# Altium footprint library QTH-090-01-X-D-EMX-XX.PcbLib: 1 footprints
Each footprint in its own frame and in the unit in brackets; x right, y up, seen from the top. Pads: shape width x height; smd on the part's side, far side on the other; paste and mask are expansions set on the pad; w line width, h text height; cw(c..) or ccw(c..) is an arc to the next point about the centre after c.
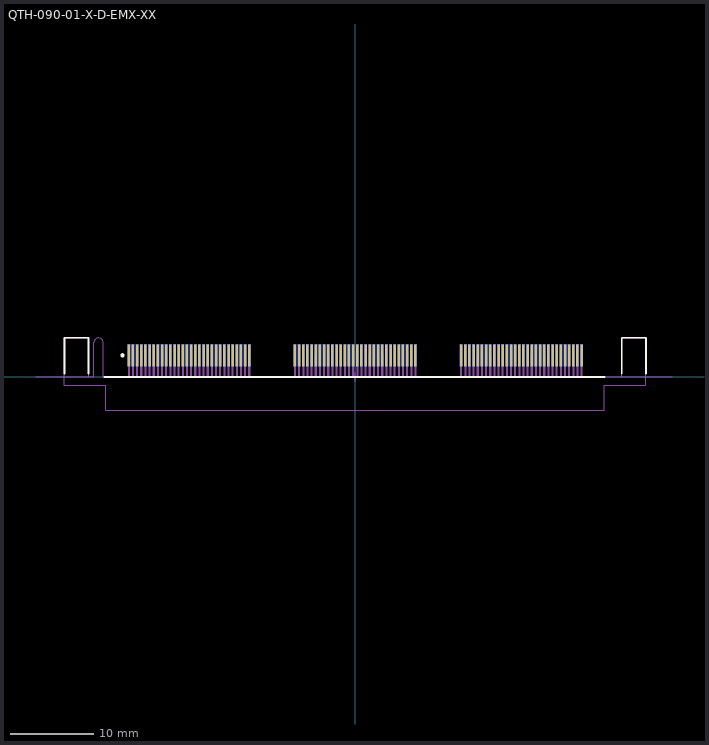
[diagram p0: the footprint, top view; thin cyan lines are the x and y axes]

## QTH-090-01-X-D-EMX-XX [mm] "0.50mm pitch, 180 pin, high speed terminal; w/edge mounts"
height 3.62
pads (180):
  rect 0.3x2.65 smd mask+0: 1(-27.253,2.6) 3(-26.753,2.6) 5(-26.253,2.6) 7(-25.753,2.6) 9(-25.253,2.6) 11(-24.753,2.6) 13(-24.253,2.6) 15(-23.753,2.6) 17(-23.253,2.6) 19(-22.753,2.6) 21(-22.253,2.6) 23(-21.753,2.6) 25(-21.253,2.6) 27(-20.753,2.6) 29(-20.253,2.6) 31(-19.753,2.6) 33(-19.253,2.6) 35(-18.753,2.6) 37(-18.253,2.6) 39(-17.753,2.6) 41(-17.253,2.6) 43(-16.753,2.6) 45(-16.253,2.6) 47(-15.753,2.6) 49(-15.253,2.6) 51(-14.753,2.6) 53(-14.253,2.6) 55(-13.753,2.6) 57(-13.253,2.6) 59(-12.753,2.6) 61(-7.25,2.6) 63(-6.75,2.6) 65(-6.25,2.6) 67(-5.75,2.6) 69(-5.25,2.6) 71(-4.75,2.6) 73(-4.25,2.6) 75(-3.75,2.6) 77(-3.25,2.6) 79(-2.75,2.6) 81(-2.25,2.6) 83(-1.75,2.6) 85(-1.25,2.6) 87(-0.75,2.6) 89(-0.25,2.6) 91(0.25,2.6) 93(0.75,2.6) 95(1.25,2.6) 97(1.75,2.6) 99(2.25,2.6) 101(2.75,2.6) 103(3.25,2.6) 105(3.75,2.6) 107(4.25,2.6) 109(4.75,2.6) 111(5.25,2.6) 113(5.75,2.6) 115(6.25,2.6) 117(6.75,2.6) 119(7.25,2.6) 121(12.753,2.6) 123(13.253,2.6) 125(13.753,2.6) 127(14.253,2.6) 129(14.753,2.6) 131(15.253,2.6) 133(15.753,2.6) 135(16.253,2.6) 137(16.753,2.6) 139(17.253,2.6) 141(17.753,2.6) 143(18.253,2.6) 145(18.753,2.6) 147(19.253,2.6) 149(19.753,2.6) 151(20.253,2.6) 153(20.753,2.6) 155(21.253,2.6) 157(21.753,2.6) 159(22.253,2.6) 161(22.753,2.6) 163(23.253,2.6) 165(23.753,2.6) 167(24.253,2.6) 169(24.753,2.6) 171(25.253,2.6) 173(25.753,2.6) 175(26.253,2.6) 177(26.753,2.6) 179(27.253,2.6)
  rect 0.3x2.65 smd far side mask+0: 2(-27.253,2.6) 4(-26.753,2.6) 6(-26.253,2.6) 8(-25.753,2.6) 10(-25.253,2.6) 12(-24.753,2.6) 14(-24.253,2.6) 16(-23.753,2.6) 18(-23.253,2.6) 20(-22.753,2.6) 22(-22.253,2.6) 24(-21.753,2.6) 26(-21.253,2.6) 28(-20.753,2.6) 30(-20.253,2.6) 32(-19.753,2.6) 34(-19.253,2.6) 36(-18.753,2.6) 38(-18.253,2.6) 40(-17.753,2.6) 42(-17.253,2.6) 44(-16.753,2.6) 46(-16.253,2.6) 48(-15.753,2.6) 50(-15.253,2.6) 52(-14.753,2.6) 54(-14.253,2.6) 56(-13.753,2.6) 58(-13.253,2.6) 60(-12.753,2.6) 62(-7.25,2.6) 64(-6.75,2.6) 66(-6.25,2.6) 68(-5.75,2.6) 70(-5.25,2.6) 72(-4.75,2.6) 74(-4.25,2.6) 76(-3.75,2.6) 78(-3.25,2.6) 80(-2.75,2.6) 82(-2.25,2.6) 84(-1.75,2.6) 86(-1.25,2.6) 88(-0.75,2.6) 90(-0.25,2.6) 92(0.25,2.6) 94(0.75,2.6) 96(1.25,2.6) 98(1.75,2.6) 100(2.25,2.6) 102(2.75,2.6) 104(3.25,2.6) 106(3.75,2.6) 108(4.25,2.6) 110(4.75,2.6) 112(5.25,2.6) 114(5.75,2.6) 116(6.25,2.6) 118(6.75,2.6) 120(7.25,2.6) 122(12.753,2.6) 124(13.253,2.6) 126(13.753,2.6) 128(14.253,2.6) 130(14.753,2.6) 132(15.253,2.6) 134(15.753,2.6) 136(16.253,2.6) 138(16.753,2.6) 140(17.253,2.6) 142(17.753,2.6) 144(18.253,2.6) 146(18.753,2.6) 148(19.253,2.6) 150(19.753,2.6) 152(20.253,2.6) 154(20.753,2.6) 156(21.253,2.6) 158(21.753,2.6) 160(22.253,2.6) 162(22.753,2.6) 164(23.253,2.6) 166(23.753,2.6) 168(24.253,2.6) 170(24.753,2.6) 172(25.253,2.6) 174(25.753,2.6) 176(26.253,2.6) 178(26.753,2.6) 180(27.253,2.6)
Top Overlay:
  circle w0.25: c-28,2.6 r0.125
  lines w0.2: -35,0.4 -35,4.7 -32.1,4.7 -32.1,0.4 ; 32.1,0.4 32.1,4.7 35,4.7 35,0.4
  lines w0.25: -30.197,0 30.003,0
Top Paste:
  lines w0.4: -30.217,0 30.003,0
Bottom Paste:
  lines w0.4: -30.217,0 30.003,0
Top Solder:
  lines w0.127: -27.253,2.603 -27.253,3.936 ; -26.753,2.603 -26.753,3.936 ; -26.253,2.603 -26.253,3.936 ; -25.753,2.603 -25.753,3.936 ; -25.253,2.603 -25.253,3.936 ; -24.753,2.603 -24.753,3.936 ; -24.253,2.603 -24.253,3.936 ; -23.753,2.603 -23.753,3.936 ; -23.253,2.603 -23.253,3.936 ; -22.753,2.603 -22.753,3.936 ; -22.253,2.603 -22.253,3.936 ; -21.753,2.603 -21.753,3.936 ; -21.253,2.603 -21.253,3.936 ; -20.753,2.603 -20.753,3.936 ; -20.253,2.603 -20.253,3.936 ; -19.753,2.603 -19.753,3.936 ; -19.253,2.603 -19.253,3.936 ; -18.753,2.603 -18.753,3.936 ; -18.253,2.603 -18.253,3.936 ; -17.753,2.603 -17.753,3.936 ; -17.253,2.603 -17.253,3.936 ; -16.753,2.603 -16.753,3.936 ; -16.253,2.603 -16.253,3.936 ; -15.753,2.603 -15.753,3.936 ; -15.253,2.603 -15.253,3.936 ; -14.753,2.603 -14.753,3.936 ; -14.253,2.603 -14.253,3.936 ; -13.753,2.603 -13.753,3.936 ; -13.253,2.603 -13.253,3.936 ; -12.753,2.603 -12.753,3.936 ; -7.25,2.603 -7.25,3.936 ; -6.75,2.603 -6.75,3.936 ; -6.25,2.603 -6.25,3.936 ; -5.75,2.603 -5.75,3.936 ; -5.25,2.603 -5.25,3.936 ; -4.75,2.603 -4.75,3.936 ; -4.25,2.603 -4.25,3.936 ; -3.75,2.603 -3.75,3.936 ; -3.25,2.603 -3.25,3.936 ; -2.75,2.603 -2.75,3.936 ; -2.25,2.603 -2.25,3.936 ; -1.75,2.603 -1.75,3.936 ; -1.25,2.603 -1.25,3.936 ; -0.75,2.603 -0.75,3.936 ; -0.25,2.603 -0.25,3.936 ; 0.25,2.603 0.25,3.936 ; 0.75,2.603 0.75,3.936 ; 1.25,2.603 1.25,3.936 ; 1.75,2.603 1.75,3.936 ; 2.25,2.603 2.25,3.936 ; 2.75,2.603 2.75,3.936 ; 3.25,2.603 3.25,3.936 ; 3.75,2.603 3.75,3.936 ; 4.25,2.603 4.25,3.936 ; 4.75,2.603 4.75,3.936 ; 5.25,2.603 5.25,3.936 ; 5.75,2.603 5.75,3.936 ; 6.25,2.603 6.25,3.936 ; 6.75,2.603 6.75,3.936 ; 7.25,2.603 7.25,3.936 ; 12.753,2.603 12.753,3.936 ; 13.253,2.603 13.253,3.936 ; 13.753,2.603 13.753,3.936 ; 14.253,2.603 14.253,3.936 ; 14.753,2.603 14.753,3.936 ; 15.253,2.603 15.253,3.936 ; 15.753,2.603 15.753,3.936 ; 16.253,2.603 16.253,3.936 ; 16.753,2.603 16.753,3.936 ; 17.253,2.603 17.253,3.936 ; 17.753,2.603 17.753,3.936 ; 18.253,2.603 18.253,3.936 ; 18.753,2.603 18.753,3.936 ; 19.253,2.603 19.253,3.936 ; 19.753,2.603 19.753,3.936 ; 20.253,2.603 20.253,3.936 ; 20.753,2.603 20.753,3.936 ; 21.253,2.603 21.253,3.936 ; 21.753,2.603 21.753,3.936 ; 22.253,2.603 22.253,3.936 ; 22.753,2.603 22.753,3.936 ; 23.253,2.603 23.253,3.936 ; 23.753,2.603 23.753,3.936 ; 24.253,2.603 24.253,3.936 ; 24.753,2.603 24.753,3.936 ; 25.253,2.603 25.253,3.936 ; 25.753,2.603 25.753,3.936 ; 26.253,2.603 26.253,3.936 ; 26.753,2.603 26.753,3.936 ; 27.253,2.603 27.253,3.936
Bottom Solder:
  lines w0.127: -27.253,2.603 -27.253,3.936 ; -26.753,2.603 -26.753,3.936 ; -26.253,2.603 -26.253,3.936 ; -25.753,2.603 -25.753,3.936 ; -25.253,2.603 -25.253,3.936 ; -24.753,2.603 -24.753,3.936 ; -24.253,2.603 -24.253,3.936 ; -23.753,2.603 -23.753,3.936 ; -23.253,2.603 -23.253,3.936 ; -22.753,2.603 -22.753,3.936 ; -22.253,2.603 -22.253,3.936 ; -21.753,2.603 -21.753,3.936 ; -21.253,2.603 -21.253,3.936 ; -20.753,2.603 -20.753,3.936 ; -20.253,2.603 -20.253,3.936 ; -19.753,2.603 -19.753,3.936 ; -19.253,2.603 -19.253,3.936 ; -18.753,2.603 -18.753,3.936 ; -18.253,2.603 -18.253,3.936 ; -17.753,2.603 -17.753,3.936 ; -17.253,2.603 -17.253,3.936 ; -16.753,2.603 -16.753,3.936 ; -16.253,2.603 -16.253,3.936 ; -15.753,2.603 -15.753,3.936 ; -15.253,2.603 -15.253,3.936 ; -14.753,2.603 -14.753,3.936 ; -14.253,2.603 -14.253,3.936 ; -13.753,2.603 -13.753,3.936 ; -13.253,2.603 -13.253,3.936 ; -12.753,2.603 -12.753,3.936 ; -7.25,2.603 -7.25,3.936 ; -6.75,2.603 -6.75,3.936 ; -6.25,2.603 -6.25,3.936 ; -5.75,2.603 -5.75,3.936 ; -5.25,2.603 -5.25,3.936 ; -4.75,2.603 -4.75,3.936 ; -4.25,2.603 -4.25,3.936 ; -3.75,2.603 -3.75,3.936 ; -3.25,2.603 -3.25,3.936 ; -2.75,2.603 -2.75,3.936 ; -2.25,2.603 -2.25,3.936 ; -1.75,2.603 -1.75,3.936 ; -1.25,2.603 -1.25,3.936 ; -0.75,2.603 -0.75,3.936 ; -0.25,2.603 -0.25,3.936 ; 0.25,2.603 0.25,3.936 ; 0.75,2.603 0.75,3.936 ; 1.25,2.603 1.25,3.936 ; 1.75,2.603 1.75,3.936 ; 2.25,2.603 2.25,3.936 ; 2.75,2.603 2.75,3.936 ; 3.25,2.603 3.25,3.936 ; 3.75,2.603 3.75,3.936 ; 4.25,2.603 4.25,3.936 ; 4.75,2.603 4.75,3.936 ; 5.25,2.603 5.25,3.936 ; 5.75,2.603 5.75,3.936 ; 6.25,2.603 6.25,3.936 ; 6.75,2.603 6.75,3.936 ; 7.25,2.603 7.25,3.936 ; 12.753,2.603 12.753,3.936 ; 13.253,2.603 13.253,3.936 ; 13.753,2.603 13.753,3.936 ; 14.253,2.603 14.253,3.936 ; 14.753,2.603 14.753,3.936 ; 15.253,2.603 15.253,3.936 ; 15.753,2.603 15.753,3.936 ; 16.253,2.603 16.253,3.936 ; 16.753,2.603 16.753,3.936 ; 17.253,2.603 17.253,3.936 ; 17.753,2.603 17.753,3.936 ; 18.253,2.603 18.253,3.936 ; 18.753,2.603 18.753,3.936 ; 19.253,2.603 19.253,3.936 ; 19.753,2.603 19.753,3.936 ; 20.253,2.603 20.253,3.936 ; 20.753,2.603 20.753,3.936 ; 21.253,2.603 21.253,3.936 ; 21.753,2.603 21.753,3.936 ; 22.253,2.603 22.253,3.936 ; 22.753,2.603 22.753,3.936 ; 23.253,2.603 23.253,3.936 ; 23.753,2.603 23.753,3.936 ; 24.253,2.603 24.253,3.936 ; 24.753,2.603 24.753,3.936 ; 25.253,2.603 25.253,3.936 ; 25.753,2.603 25.753,3.936 ; 26.253,2.603 26.253,3.936 ; 26.753,2.603 26.753,3.936 ; 27.253,2.603 27.253,3.936
Mechanical 4:
  lines w0.254: -30.217,0 30.003,0
Mechanical 12:
  lines w0.001: -38.447,0 -31.447,0 -31.447,4.15 ; -30.347,4.15 -30.347,0 38.153,0
Mechanical 13:
  lines w0.1: -35,-1 -35,4.7 -32.1,4.7 -32.1,0 -31.447,0 -31.447,4.15 cw(c-30.897,4.15) -30.347,4.15 -30.347,0 32.1,0 32.1,4.7 35,4.7 35,-1 30,-1 30,-4 -30,-4 -30,-1 -35,-1
  lines w0.25: -27.253,0.003 -27.253,2.603 ; -26.753,0.003 -26.753,2.603 ; -26.253,0.003 -26.253,2.603 ; -25.753,0.003 -25.753,2.603 ; -25.253,0.003 -25.253,2.603 ; -24.753,0.003 -24.753,2.603 ; -24.253,0.003 -24.253,2.603 ; -23.753,0.003 -23.753,2.603 ; -23.253,0.003 -23.253,2.603 ; -22.753,0.003 -22.753,2.603 ; -22.253,0.003 -22.253,2.603 ; -21.753,0.003 -21.753,2.603 ; -21.253,0.003 -21.253,2.603 ; -20.753,0.003 -20.753,2.603 ; -20.253,0.003 -20.253,2.603 ; -19.753,0.003 -19.753,2.603 ; -19.253,0.003 -19.253,2.603 ; -18.753,0.003 -18.753,2.603 ; -18.253,0.003 -18.253,2.603 ; -17.753,0.003 -17.753,2.603 ; -17.253,0.003 -17.253,2.603 ; -16.753,0.003 -16.753,2.603 ; -16.253,0.003 -16.253,2.603 ; -15.753,0.003 -15.753,2.603 ; -15.253,0.003 -15.253,2.603 ; -14.753,0.003 -14.753,2.603 ; -14.253,0.003 -14.253,2.603 ; -13.753,0.003 -13.753,2.603 ; -13.253,0.003 -13.253,2.603 ; -12.753,0.003 -12.753,2.603 ; -7.25,0.003 -7.25,2.603 ; -6.75,0.003 -6.75,2.603 ; -6.25,0.003 -6.25,2.603 ; -5.75,0.003 -5.75,2.603 ; -5.25,0.003 -5.25,2.603 ; -4.75,0.003 -4.75,2.603 ; -4.25,0.003 -4.25,2.603 ; -3.75,0.003 -3.75,2.603 ; -3.25,0.003 -3.25,2.603 ; -2.75,0.003 -2.75,2.603 ; -2.25,0.003 -2.25,2.603 ; -1.75,0.003 -1.75,2.603 ; -1.25,0.003 -1.25,2.603 ; -0.75,0.003 -0.75,2.603 ; -0.25,0.003 -0.25,2.603 ; 0.25,0.003 0.25,2.603 ; 0.75,0.003 0.75,2.603 ; 1.25,0.003 1.25,2.603 ; 1.75,0.003 1.75,2.603 ; 2.25,0.003 2.25,2.603 ; 2.75,0.003 2.75,2.603 ; 3.25,0.003 3.25,2.603 ; 3.75,0.003 3.75,2.603 ; 4.25,0.003 4.25,2.603 ; 4.75,0.003 4.75,2.603 ; 5.25,0.003 5.25,2.603 ; 5.75,0.003 5.75,2.603 ; 6.25,0.003 6.25,2.603 ; 6.75,0.003 6.75,2.603 ; 7.25,0.003 7.25,2.603 ; 12.753,0.003 12.753,2.603 ; 13.253,0.003 13.253,2.603 ; 13.753,0.003 13.753,2.603 ; 14.253,0.003 14.253,2.603 ; 14.753,0.003 14.753,2.603 ; 15.253,0.003 15.253,2.603 ; 15.753,0.003 15.753,2.603 ; 16.253,0.003 16.253,2.603 ; 16.753,0.003 16.753,2.603 ; 17.253,0.003 17.253,2.603 ; 17.753,0.003 17.753,2.603 ; 18.253,0.003 18.253,2.603 ; 18.753,0.003 18.753,2.603 ; 19.253,0.003 19.253,2.603 ; 19.753,0.003 19.753,2.603 ; 20.253,0.003 20.253,2.603 ; 20.753,0.003 20.753,2.603 ; 21.253,0.003 21.253,2.603 ; 21.753,0.003 21.753,2.603 ; 22.253,0.003 22.253,2.603 ; 22.753,0.003 22.753,2.603 ; 23.253,0.003 23.253,2.603 ; 23.753,0.003 23.753,2.603 ; 24.253,0.003 24.253,2.603 ; 24.753,0.003 24.753,2.603 ; 25.253,0.003 25.253,2.603 ; 25.753,0.003 25.753,2.603 ; 26.253,0.003 26.253,2.603 ; 26.753,0.003 26.753,2.603 ; 27.253,0.003 27.253,2.603
  text ".Designator" at 0,0 h1.52
Mechanical 15:
  lines w0.05: -0.5,0 0.5,0 ; 0,-0.5 0,0.5
Drill Drawing:
  lines w0.001: -31.447,4.15 cw(c-30.897,4.15) -30.347,4.15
